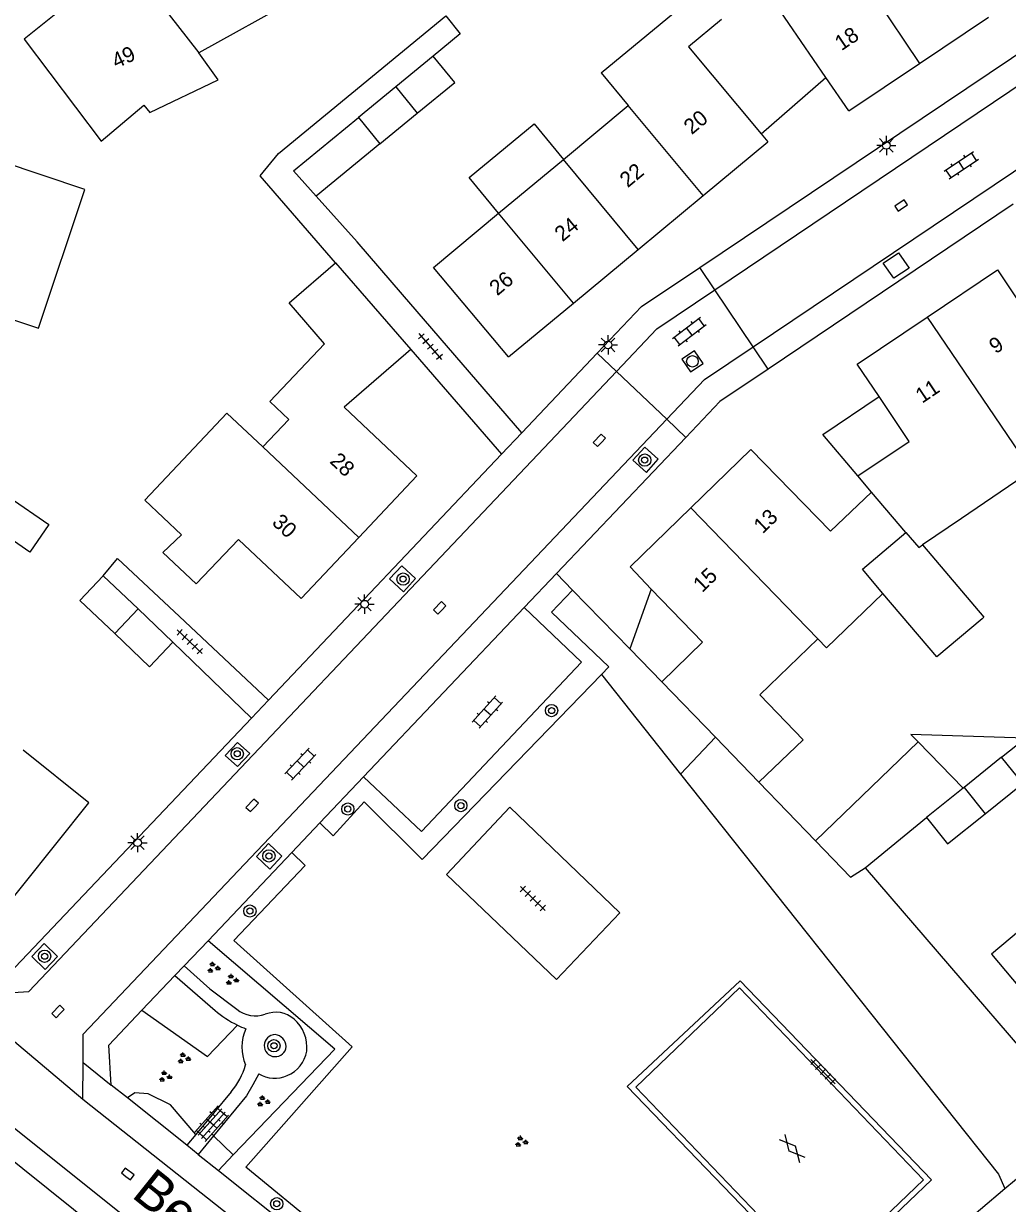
# Model space of a CAD drawing. Extents: x 136000 to 141014, y 402000 to 403500.
# Drawn here: x 137196.5 to 137260.6, y 402087.3 to 402164.2 of the extents above; entities that cross this region are included whole.
import ezdxf

# ---------------------------------------------------------------- set-up
doc = ezdxf.new("R2010")
doc.units = 0
for name, color, linetype in [('gg-afsc-erfafscheiding', 7, 'Continuous'), ('gg-afsc-muur', 7, 'Continuous'), ('gg-anno-huisnummerreeks BGT', 7, 'Continuous'), ('gg-anno-openbare ruimte label', 7, 'Continuous'), ('gg-bbg-bijgebouw', 7, 'Continuous'), ('gg-bbg-gedigitaliseerde bebouwing', 7, 'Continuous'), ('gg-bbg-gedigitaliseerde bijgebouw', 7, 'Continuous'), ('gg-bbg-hoofdgebouw', 7, 'Continuous'), ('gg-bbg-luifel en loopbrug', 7, 'Continuous'), ('gg-bbg-tussenscheiding', 7, 'Continuous'), ('gg-knt-verharding', 7, 'Continuous'), ('gg-knt-verharding nz', 7, 'Continuous'), ('gt-grn-groengrens', 7, 'Continuous'), ('gt-grn-weggrens', 7, 'Continuous'), ('gt-symb-boom', 7, 'Continuous'), ('gt-symb-gesloten verharding', 7, 'Continuous'), ('gt-symb-groenvak', 7, 'Continuous'), ('gt-symb-klinker verharding', 7, 'Continuous'), ('gt-symb-kolk', 7, 'Continuous'), ('gt-symb-lichtmast', 7, 'Continuous'), ('gt-symb-rioolschacht', 7, 'Continuous'), ('gt-symb-tegel verharding', 7, 'Continuous')]:
    doc.layers.add(name, color=color, linetype=linetype)

# ---------------------------------------------------------------- blocks, each defined once
blk = doc.blocks.new('gt0-KOLK')
at = {"layer": 'gt-symb-kolk'}
blk.add_lwpolyline([(0, 0), (0.375, 0), (0.375, 0.4), (-0.375, 0.4), (-0.375, 0), (0, 0)], dxfattribs=at)
blk = doc.blocks.new('gt0-KL1')
at = {"layer": 'gt-symb-klinker verharding'}
for p, q in [((-1.15, 0.3), (1.15, 0.3)), ((-1, -0.3), (-1, 0.3)), ((-0.5, 0.3), (-0.5, 0.45)), ((0, -0.3), (0, 0.3)), ((0.5, 0.3), (0.5, 0.45)), ((1, -0.3), (1, 0.3)), ((-1.15, -0.3), (1.15, -0.3)), ((-0.5, -0.45), (-0.5, -0.3)), ((0.5, -0.45), (0.5, -0.3))]:
    blk.add_line(p, q, dxfattribs=at)
blk = doc.blocks.new('gt0-LMAST')
at = {"layer": 'gt-symb-lichtmast'}
for p, q in [((-0.182, 0.173), (-0.447, 0.438)), ((-0.005, 0.246), (-0.005, 0.621)), ((0.172, 0.173), (0.437, 0.438)), ((-0.255, -0.004), (-0.63, -0.004)), ((-0.182, -0.181), (-0.447, -0.446)), ((-0.005, -0.254), (-0.005, -0.629)), ((0.437, -0.446), (0.172, -0.181)), ((0.245, -0.004), (0.62, -0.004))]:
    blk.add_line(p, q, dxfattribs=at)
blk.add_circle((-0.005, -0.004), 0.25, dxfattribs=at)
blk = doc.blocks.new('gt0-TEG1')
at = {"layer": 'gt-symb-tegel verharding'}
for p, q in [((-1.125, 0), (1.125, 0)), ((-0.9, -0.25), (-0.9, 0.25)), ((-0.45, -0.25), (-0.45, 0.25)), ((0, -0.25), (0, 0.25)), ((0.45, -0.25), (0.45, 0.25)), ((0.9, -0.25), (0.9, 0.25))]:
    blk.add_line(p, q, dxfattribs=at)
blk = doc.blocks.new('gt0-BOOM')
at = {"layer": 'gt-symb-boom'}
for radius in [0.4, 0.2]:
    blk.add_circle((0, 0), radius, dxfattribs=at)
blk = doc.blocks.new('gt0-RS')
at = {"layer": 'gt-symb-rioolschacht'}
blk.add_lwpolyline([(-0.5, -0.5), (0.5, -0.5), (0.5, 0.5), (-0.5, 0.5)], close=True, dxfattribs=at)
blk.add_circle((0, 0), 0.375, dxfattribs=at)
blk = doc.blocks.new('gt0-GRVAK')
at = {"layer": 'gt-symb-groenvak'}
for p, q in [((-0.11, 0.189), (-0.228, 0.24)), ((-0.182, 0.153), (0.088, 0.153)), ((-0.091, 0.211), (-0.156, 0.322)), ((-0.047, 0.214), (-0.047, 0.393)), ((-0.004, 0.211), (0.061, 0.322)), ((0.015, 0.189), (0.133, 0.24)), ((0.262, -0.052), (0.197, 0.059)), ((0.305, -0.049), (0.305, 0.13)), ((0.349, -0.052), (0.414, 0.059)), ((-0.245, -0.228), (-0.363, -0.177)), ((-0.318, -0.264), (-0.047, -0.264)), ((-0.226, -0.206), (-0.291, -0.095)), ((-0.183, -0.203), (-0.183, -0.024)), ((-0.139, -0.206), (-0.074, -0.095)), ((-0.12, -0.228), (-0.002, -0.177)), ((0.243, -0.074), (0.125, -0.023)), ((0.17, -0.11), (0.441, -0.11)), ((0.368, -0.074), (0.486, -0.023))]:
    blk.add_line(p, q, dxfattribs=at)
blk = doc.blocks.new('gt0-GESVH1')
at = {"layer": 'gt-symb-gesloten verharding'}
for p, q in [((-0.992, -0.261), (0.008, 0.239)), ((0.008, -0.261), (-0.992, 0.239)), ((0.008, 0.239), (1.008, -0.261)), ((1.008, 0.239), (0.008, -0.261))]:
    blk.add_line(p, q, dxfattribs=at)

msp = doc.modelspace()

# ---------------------------------------------------------------- linework, layer by layer
at = {"layer": 'gg-afsc-erfafscheiding'}
for p, q in [((137218.185, 402150.014), (137215.522, 402153.002)), ((137221.155, 402146.585), (137218.185, 402150.014)), ((137231.182, 402128.39), (137232.229, 402127.315)), ((137232.229, 402127.315), (137235.962, 402123.483)), ((137251.296, 402109.209), (137265.538, 402092.614))]:
    msp.add_line(p, q, dxfattribs=at)
msp.add_lwpolyline([(137216.788, 402148.647), (137211.879, 402154.311), (137213.07, 402155.77), (137223.96, 402164.738), (137224.913, 402163.577), (137223.14, 402162.12)], dxfattribs=at)
at = {"layer": 'gg-afsc-muur'}
msp.add_line((137244.366, 402114.792), (137248.054, 402110.974), dxfattribs=at)
msp.add_lwpolyline([(137201.651, 402128.242), (137202.583, 402129.373), (137206.627, 402125.593)], dxfattribs=at)
at = {"layer": 'gg-bbg-bijgebouw'}
for p, q in [((137203.915, 402126.083), (137201.651, 402128.242)), ((137206.189, 402123.913), (137203.915, 402126.083))]:
    msp.add_line(p, q, dxfattribs=at)
at = {"layer": 'gg-bbg-gedigitaliseerde bebouwing'}
for p, q in [((137234.091, 402161.025), (137240.455, 402166.305)), ((137234.091, 402161.025), (137235.858, 402158.896)), ((137231.635, 402155.393), (137235.858, 402158.896)), ((137244.511, 402157.058), (137244.95, 402156.53)), ((137227.412, 402151.89), (137231.635, 402155.393)), ((137262.121, 402135.083), (137257.567, 402131.974)), ((137257.567, 402131.974), (137255.032, 402130.265)), ((137238.05, 402121.34), (137241.545, 402117.716)), ((137241.545, 402117.716), (137244.366, 402114.792))]:
    msp.add_line(p, q, dxfattribs=at)
for points in [[(137214.905, 402167.188), (137215.286, 402166.693), (137214.147, 402165.825), (137207.878, 402162.339)], [(137241.922, 402164.501), (137239.792, 402162.729), (137244.511, 402157.058)], [(137196.494, 402163.222), (137201.525, 402156.574), (137204.289, 402158.919), (137204.684, 402158.453), (137209.148, 402160.57), (137207.878, 402162.339)], [(137190.074, 402138.976), (137190.981, 402141.713), (137190.569, 402141.851), (137192.022, 402146.191), (137197.441, 402144.383), (137200.453, 402153.42), (137186.731, 402158.042)], [(137212.04, 402136.645), (137213.737, 402138.439), (137212.504, 402139.605), (137216.07, 402143.371), (137213.766, 402146.03), (137216.788, 402148.647)], [(137212.04, 402136.645), (137209.707, 402138.841), (137204.364, 402133.165), (137206.758, 402130.912)], [(137248.213, 402124.141), (137248.778, 402123.555), (137252.453, 402127.095)], [(137244.366, 402114.792), (137247.247, 402117.56), (137244.425, 402120.492), (137248.213, 402124.141)], [(137263.721, 402107.109), (137259.53, 402103.59), (137266.12, 402095.72)]]:
    msp.add_lwpolyline(points, dxfattribs=at)
at = {"layer": 'gg-bbg-gedigitaliseerde bijgebouw'}
for p, q in [((137223.14, 402162.12), (137220.705, 402160.12)), ((137220.705, 402160.12), (137218.27, 402158.12)), ((137218.27, 402158.12), (137219.67, 402156.4)), ((137219.67, 402156.4), (137222.112, 402158.407)), ((137260.184, 402116.428), (137257.735, 402114.455)), ((137257.671, 402114.403), (137255.28, 402112.49)), ((137257.735, 402114.455), (137257.671, 402114.403))]:
    msp.add_line(p, q, dxfattribs=at)
for points in [[(137222.112, 402158.407), (137224.55, 402160.41), (137223.14, 402162.12)], [(137195.516, 402133.379), (137198.101, 402131.593), (137196.858, 402129.791), (137194.272, 402131.577)], [(137255.032, 402130.265), (137259.027, 402125.544), (137258.914, 402125.449)], [(137202.396, 402124.485), (137200.128, 402126.64), (137201.651, 402128.242)], [(137258.914, 402125.449), (137255.967, 402122.957), (137252.453, 402127.095)], [(137202.396, 402124.485), (137204.674, 402122.319), (137206.189, 402123.913)], [(137259.113, 402112.733), (137261.57, 402114.7), (137260.184, 402116.428)], [(137255.28, 402112.49), (137256.66, 402110.77), (137259.113, 402112.733)]]:
    msp.add_lwpolyline(points, dxfattribs=at)
at = {"layer": 'gg-bbg-hoofdgebouw'}
for p, q in [((137248.732, 402160.736), (137245.518, 402165.424)), ((137254.838, 402161.64), (137259.332, 402164.655)), ((137250.23, 402158.55), (137254.838, 402161.64)), ((137250.23, 402158.55), (137248.732, 402160.736)), ((137240.727, 402153.027), (137244.95, 402156.53)), ((137236.504, 402149.524), (137240.727, 402153.027)), ((137232.281, 402146.021), (137236.504, 402149.524)), ((137216.788, 402148.647), (137221.684, 402143.006)), ((137228.06, 402142.52), (137232.281, 402146.021)), ((137250.78, 402142.04), (137255.338, 402145.105)), ((137252.195, 402139.935), (137250.78, 402142.04)), ((137243.85, 402136.48), (137239.93, 402132.67)), ((137243.85, 402136.48), (137249.031, 402131.15)), ((137222.08, 402134.76), (137218.294, 402130.743)), ((137251.708, 402133.705), (137250.823, 402134.754)), ((137249.031, 402131.15), (137251.708, 402133.705)), ((137218.294, 402130.743), (137214.54, 402126.76))]:
    msp.add_line(p, q, dxfattribs=at)
for points in [[(137196.587, 402167.787), (137198.779, 402165.043), (137196.494, 402163.222)], [(137228.06, 402142.52), (137223.177, 402148.352), (137227.412, 402151.89)], [(137255.338, 402145.105), (137259.91, 402148.18), (137261.308, 402146.098)], [(137221.684, 402143.006), (137217.342, 402139.229), (137222.08, 402134.76)], [(137250.823, 402134.754), (137254.167, 402137.003), (137252.195, 402139.935)], [(137239.93, 402132.67), (137235.97, 402128.82), (137237.358, 402127.38)], [(137214.54, 402126.76), (137210.466, 402130.62), (137207.707, 402127.716), (137205.525, 402129.77), (137206.758, 402130.912)], [(137237.358, 402127.38), (137240.69, 402123.92), (137238.05, 402121.34)], [(137189.953, 402108.774), (137194.228, 402105.355), (137200.704, 402113.451), (137196.428, 402116.871)]]:
    msp.add_lwpolyline(points, dxfattribs=at)
at = {"layer": 'gg-bbg-luifel en loopbrug'}
for p, q in [((137244.511, 402157.058), (137248.732, 402160.736)), ((137219.67, 402156.4), (137215.522, 402153.002)), ((137237.358, 402127.38), (137235.962, 402123.483)), ((137235.962, 402123.483), (137238.05, 402121.34)), ((137248.054, 402110.974), (137254.743, 402117.417)), ((137254.743, 402117.417), (137257.671, 402114.403)), ((137251.296, 402109.209), (137255.28, 402112.49))]:
    msp.add_line(p, q, dxfattribs=at)
for points in [[(137215.522, 402153.002), (137214.05, 402154.654), (137218.27, 402158.12)], [(137227.412, 402151.89), (137225.497, 402154.199), (137229.719, 402157.702), (137231.635, 402155.393)], [(137250.823, 402134.754), (137248.539, 402137.462), (137252.195, 402139.935)], [(137260.184, 402116.428), (137261.728, 402117.67), (137254.273, 402117.901), (137254.743, 402117.417)], [(137248.054, 402110.974), (137250.347, 402108.6), (137251.296, 402109.209)]]:
    msp.add_lwpolyline(points, dxfattribs=at)
at = {"layer": 'gg-bbg-tussenscheiding'}
for p, q in [((137248.145, 402171.605), (137254.838, 402161.64)), ((137220.705, 402160.12), (137222.112, 402158.407)), ((137240.727, 402153.027), (137235.858, 402158.896)), ((137236.504, 402149.524), (137231.635, 402155.393)), ((137232.281, 402146.021), (137227.412, 402151.89)), ((137255.338, 402145.105), (137262.121, 402135.083)), ((137218.294, 402130.743), (137212.04, 402136.645)), ((137253.937, 402131.062), (137251.708, 402133.705)), ((137248.213, 402124.141), (137239.93, 402132.67)), ((137203.915, 402126.083), (137202.396, 402124.485)), ((137257.735, 402114.455), (137259.113, 402112.733))]:
    msp.add_line(p, q, dxfattribs=at)
for points in [[(137200.222, 402172.153), (137206.479, 402164.114), (137207.878, 402162.339)], [(137252.453, 402127.095), (137251.117, 402128.667), (137253.937, 402131.062)], [(137253.937, 402131.062), (137254.799, 402130.093), (137255.032, 402130.265)]]:
    msp.add_lwpolyline(points, dxfattribs=at)
at = {"layer": 'gg-knt-verharding'}
for p, q in [((137240.512, 402148.349), (137272.753, 402170.015)), ((137260.939, 402152.473), (137244.968, 402141.724)), ((137241.492, 402146.891), (137240.512, 402148.349)), ((137228.921, 402137.565), (137221.155, 402146.585)), ((137243.996, 402143.169), (137241.492, 402146.891)), ((137221.684, 402143.006), (137227.6, 402136.171)), ((137228.921, 402137.565), (137233.834, 402142.751)), ((137235.083, 402141.566), (137233.834, 402142.751)), ((137244.968, 402141.724), (137243.996, 402143.169)), ((137238.368, 402138.449), (137235.083, 402141.566)), ((137239.61, 402137.271), (137238.368, 402138.449)), ((137227.6, 402136.171), (137228.921, 402137.565)), ((137239.61, 402137.271), (137231.182, 402128.39)), ((137212.411, 402120.138), (137227.6, 402136.171)), ((137229.081, 402126.175), (137231.182, 402128.39)), ((137206.627, 402125.593), (137212.411, 402120.138)), ((137211.303, 402118.969), (137206.189, 402123.913)), ((137211.303, 402118.969), (137212.411, 402120.138)), ((137215.765, 402112.14), (137218.611, 402115.14)), ((137213.928, 402110.203), (137215.765, 402112.14)), ((137213.928, 402110.203), (137208.478, 402104.46)), ((137236.54, 402057.51), (137171.536, 402109.464)), ((137206.928, 402102.827), (137208.478, 402104.46)), ((137206.319, 402102.185), (137206.928, 402102.827)), ((137204.171, 402099.921), (137206.319, 402102.185)), ((137206.319, 402102.185), (137208.932, 402099.913)), ((137203.225, 402094.207), (137202.166, 402095.051)), ((137207.095, 402091.123), (137203.225, 402094.207)), ((137209.991, 402094.605), (137207.685, 402091.832)), ((137207.685, 402091.832), (137207.095, 402091.123)), ((137208.829, 402091.737), (137207.837, 402090.532)), ((137207.837, 402090.532), (137207.095, 402091.123)), ((137207.837, 402090.532), (137209.154, 402089.482)), ((137209.154, 402089.482), (137220.95, 402080.082))]:
    msp.add_line(p, q, dxfattribs=at)
for points in [[(137252.474, 402148.634), (137253.458, 402149.3), (137254.149, 402148.304), (137253.165, 402147.638), (137252.474, 402148.634)], [(137233.834, 402142.751), (137236.73, 402145.808), (137240.512, 402148.349)], [(137244.968, 402141.724), (137241.833, 402139.614), (137239.61, 402137.271)], [(137236.161, 402135.772), (137237.042, 402134.973), (137237.812, 402135.841), (137236.931, 402136.64), (137236.161, 402135.772)], [(137220.308, 402128.053), (137221.105, 402128.905), (137222.002, 402128.061), (137221.205, 402127.209), (137220.308, 402128.053)], [(137229.081, 402126.175), (137232.819, 402122.615), (137222.387, 402111.566), (137218.611, 402115.14)], [(137192.821, 402102.537), (137195.916, 402102.727), (137211.303, 402118.969)], [(137209.584, 402116.54), (137210.392, 402115.812), (137211.197, 402116.659), (137210.389, 402117.387), (137209.584, 402116.54)], [(137235.306, 402106.28), (137228.132, 402113.156), (137224.023, 402108.77), (137231.187, 402101.921), (137235.306, 402106.28)], [(137211.627, 402109.947), (137212.423, 402110.789), (137213.291, 402109.959), (137212.496, 402109.117), (137211.627, 402109.947)], [(137196.996, 402103.427), (137197.797, 402104.268), (137198.676, 402103.42), (137197.875, 402102.579), (137196.996, 402103.427)], [(137206.928, 402102.827), (137208.597, 402101.327), (137210.353, 402099.999)], [(137248.345, 402081.91), (137235.783, 402094.948), (137243.151, 402101.85), (137255.616, 402088.879), (137248.345, 402081.91)], [(137248.333, 402082.395), (137255.095, 402088.879), (137243.095, 402101.386), (137236.344, 402094.919), (137248.333, 402082.395)], [(137202.166, 402095.051), (137202.022, 402097.657), (137204.171, 402099.921)], [(137211.779, 402095.785), (137211.403, 402095.053), (137210.978, 402094.348), (137208.829, 402091.737)]]:
    msp.add_lwpolyline(points, dxfattribs=at)
for centre, radius, start, end in [((137213.216, 402104.844), 6.532, 229.01705, 244.38518), ((137211.583, 402101.484), 1.929, 230.36546, 288.93249), ((137212.896, 402098.014), 1.783, 48.26149, 112.65525), ((137213.302, 402105.077), 6.779, 244.58247, 249.64817), ((137213.614, 402097.519), 2.928, 155.7611, 203.16798), ((137212.486, 402097.511), 2.432, 353.86252, 48.95505), ((137212.853, 402097.616), 0.718, 89.94554, 355.51627), ((137212.749, 402097.52), 0.821, 2.79676, 82.66505), ((137212.849, 402097.603), 2.085, 292.24505, 350.2761), ((137206.254, 402097.706), 4.856, 320.3086, 343.98952), ((137212.811, 402097.433), 1.945, 237.9422, 295.16228)]:
    msp.add_arc(centre, radius, start, end, dxfattribs=at)
at = {"layer": 'gg-knt-verharding nz'}
for p, q in [((137243.996, 402143.169), (137293.836, 402176.694)), ((137218.611, 402115.14), (137229.081, 402126.175)), ((137236.866, 402059.445), (137172.601, 402110.823)), ((137200.33, 402094.097), (137200.333, 402096.519)), ((137233.87, 402067.6), (137200.33, 402094.097))]:
    msp.add_line(p, q, dxfattribs=at)
for points in [[(137241.492, 402146.891), (137300.223, 402186.478), (137300.935, 402189.541)], [(137235.083, 402141.566), (137237.716, 402144.346), (137241.492, 402146.891)], [(137238.368, 402138.449), (137240.818, 402141.032), (137243.996, 402143.169)], [(137194.723, 402101.013), (137196.811, 402101.146), (137235.083, 402141.566)], [(137200.333, 402096.519), (137200.336, 402098.363), (137238.368, 402138.449)]]:
    msp.add_lwpolyline(points, dxfattribs=at)
at = {"layer": 'gt-grn-groengrens'}
for p, q in [((137234.121, 402121.808), (137239.264, 402115.322)), ((137241.545, 402117.716), (137239.264, 402115.322)), ((137239.264, 402115.322), (137259.979, 402089.248)), ((137260.4, 402088.299), (137265.538, 402092.614)), ((137208.829, 402091.737), (137210.125, 402090.492)), ((137209.154, 402089.482), (137210.125, 402090.492)), ((137221.622, 402080.926), (137210.935, 402089.701)), ((137259.979, 402089.248), (137260.4, 402088.299)), ((137252.236, 402081.443), (137260.4, 402088.299))]:
    msp.add_line(p, q, dxfattribs=at)
for points in [[(137232.229, 402127.315), (137230.855, 402125.867), (137234.599, 402122.301), (137234.121, 402121.808)], [(137215.765, 402112.14), (137216.637, 402111.305), (137218.651, 402113.511), (137222.43, 402109.746), (137234.121, 402121.808)], [(137210.153, 402104.465), (137214.811, 402109.365), (137213.928, 402110.203)], [(137210.125, 402090.492), (137216.748, 402097.384), (137208.478, 402104.46)], [(137210.935, 402089.701), (137217.87, 402097.532), (137210.153, 402104.465)], [(137204.171, 402099.921), (137208.442, 402096.915), (137210.392, 402098.954)], [(137207.685, 402091.832), (137206.025, 402093.752), (137204.573, 402094.468), (137203.71, 402094.532), (137203.225, 402094.207)]]:
    msp.add_lwpolyline(points, dxfattribs=at)
at = {"layer": 'gt-grn-weggrens'}
for p, q in [((137200.33, 402094.097), (137192.304, 402100.86)), ((137200.333, 402096.519), (137202.166, 402095.051))]:
    msp.add_line(p, q, dxfattribs=at)

# ---------------------------------------------------------------- block references
at = {"layer": 'gt-symb-boom'}
for p in [(137236.928, 402135.785), (137221.187, 402128.031), (137230.862, 402119.461), (137210.379, 402116.645), (137217.585, 402113.043), (137224.949, 402113.263), (137212.441, 402109.983), (137211.205, 402106.394), (137197.83, 402103.447), (137212.773, 402097.611), (137212.957, 402087.31)]:
    msp.add_blockref('gt0-BOOM', p, dxfattribs=at)
at = {"layer": 'gt-symb-gesloten verharding', "rotation": -49.01346679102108}
msp.add_blockref('gt0-GESVH1', (137246.54, 402090.926), dxfattribs=at)
at = {"layer": 'gt-symb-groenvak'}
for p in [(137208.82, 402102.694), (137210.022, 402101.9), (137206.891, 402096.788), (137205.672, 402095.597), (137212.067, 402093.977), (137228.872, 402091.357)]:
    msp.add_blockref('gt0-GRVAK', p, dxfattribs=at)
at = {"layer": 'gt-symb-klinker verharding'}
for p, rotation in [((137257.555, 402155.009), 33.91251258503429), ((137239.833, 402144.166), 37.282255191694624), ((137226.68, 402119.36), 48.24275297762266), ((137214.495, 402115.974), 46.49997134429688), ((137208.605, 402092.631), 48.20456825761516), ((137208.829, 402092.431), 48.24275297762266)]:
    msp.add_blockref('gt0-KL1', p, dxfattribs=dict(at, rotation=rotation))
at = {"layer": 'gt-symb-kolk'}
for p, rotation in [((137253.749, 402152.222), 33.992039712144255), ((137234.115, 402136.94), 46.539402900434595), ((137223.713, 402126.015), 46.539402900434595), ((137211.497, 402113.144), 46.539402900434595), ((137198.843, 402099.712), 46.53940289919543), ((137203.132, 402089.096), -36.66359246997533)]:
    msp.add_blockref('gt0-KOLK', p, dxfattribs=dict(at, rotation=rotation))
at = {"layer": 'gt-symb-lichtmast'}
for p in [(137252.678, 402156.304), (137234.546, 402143.301), (137218.679, 402126.399), (137203.888, 402110.85)]:
    msp.add_blockref('gt0-LMAST', p, dxfattribs=at)
at = {"layer": 'gt-symb-rioolschacht', "rotation": 33.992039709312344}
msp.add_blockref('gt0-RS', (137240.036, 402142.225), dxfattribs=at)
at = {"layer": 'gt-symb-tegel verharding'}
for p, rotation in [((137222.964, 402143.185), 131.22904927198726), ((137207.283, 402123.947), 136.70135460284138), ((137229.638, 402107.21), -43.7035699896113), ((137248.553, 402095.92), -45.324159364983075)]:
    msp.add_blockref('gt0-TEG1', p, dxfattribs=dict(at, rotation=rotation))

# ---------------------------------------------------------------- texts
at = {"layer": 'gg-anno-huisnummerreeks BGT'}
for s, rotation, p in [('18', 33.8, (137249.742, 402162.438)), ('49', 25.3, (137202.502, 402161.292)), ('20', 39.6, (137239.991, 402156.966)), ('22', 39.6, (137235.821, 402153.507)), ('24', 39.6, (137231.573, 402149.983)), ('26', 39.6, (137227.323, 402146.458)), ('9', 33.9, (137259.795, 402142.679)), ('11', 33.9, (137255.003, 402139.457)), ('28', 316.7, (137216.356, 402135.651)), ('13', 44.2, (137244.614, 402130.945)), ('30', 316.7, (137212.586, 402131.651)), ('15', 44.2, (137240.674, 402127.115))]:
    msp.add_text(s, height=1, rotation=rotation, dxfattribs=at).set_placement(p)
at = {"layer": 'gg-anno-openbare ruimte label'}
msp.add_text('Bereklauw', height=2.5, rotation=321.4, dxfattribs=at).set_placement((137203.418, 402087.796))

doc.saveas('drawing.dxf')
